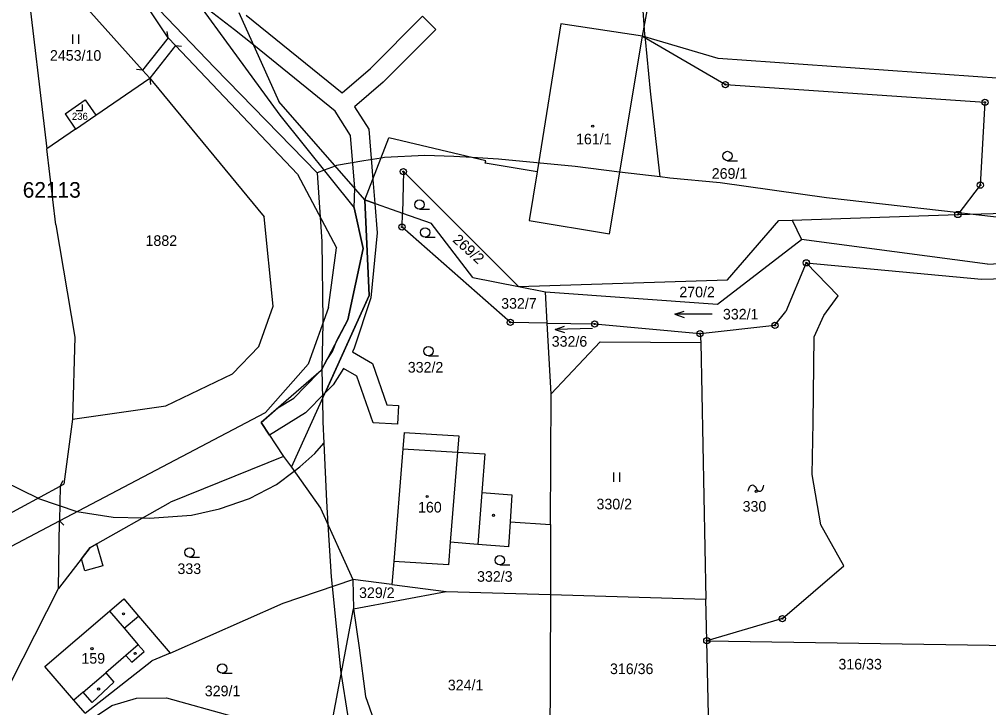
# Model space of a CAD drawing. Extents: x -546762 to -540209, y -1046851 to -1035694.
# Drawn here: x -542383.9 to -542228.7, y -1038905.5 to -1038795.4 of the extents above; entities that cross this region are included whole.
import ezdxf

# ---------------------------------------------------------------- set-up
doc = ezdxf.new("R2010")
doc.units = 0
for name, color, linetype in [('Vrstva 1', 7, 'Continuous'), ('Vrstva 18', 7, 'Continuous'), ('Vrstva 19', 7, 'Continuous'), ('Vrstva 24', 7, 'Continuous'), ('Vrstva 25', 7, 'Continuous'), ('Vrstva 26', 7, 'Continuous'), ('Vrstva 3', 7, 'Continuous'), ('Vrstva 30', 7, 'Continuous'), ('Vrstva 37', 7, 'Continuous'), ('Vrstva 4', 7, 'Continuous'), ('Vrstva 52', 7, 'Continuous'), ('Vrstva 53', 7, 'Continuous'), ('Vrstva 6', 7, 'Continuous')]:
    doc.layers.add(name, color=color, linetype=linetype)

msp = doc.modelspace()

# ---------------------------------------------------------------- linework, layer by layer
at = {"layer": 'Vrstva 1'}
for p, q in [((-542289.4, -1038829.68), (-542284.12, -1038798.06)), ((-542302.25, -1038827.55), (-542289.4, -1038829.68)), ((-542252.83, -1038839.61), (-542257.91, -1038834.34)), ((-542255.11, -1038842.75), (-542252.83, -1038839.61)), ((-542256.65, -1038846.21), (-542255.11, -1038842.75)), ((-542256.83, -1038859.88), (-542256.65, -1038846.21)), ((-542256.95, -1038868.24), (-542256.83, -1038859.88)), ((-542255.57, -1038876.26), (-542256.95, -1038868.24)), ((-542251.88, -1038882.83), (-542255.57, -1038876.26)), ((-542261.74, -1038891.29), (-542251.88, -1038882.83)), ((-542273.83, -1038894.83), (-542273.98, -1038888.19)), ((-542261.74, -1038891.29), (-542273.83, -1038894.83)), ((-542273.83, -1038894.83), (-542140.34, -1038896.94)), ((-542273.49, -1038910.46), (-542273.83, -1038894.83))]:
    msp.add_line(p, q, dxfattribs=at)
for points in [[(-542360.08, -1038798.3), (-542376.28, -1038773.87)], [(-542284.12, -1038798.06), (-542280.6, -1038779)], [(-542363.14, -1038781.96), (-542342.19, -1038810.68)], [(-542364.14, -1038803.52), (-542379.8, -1038785.97)], [(-542382.73, -1038788.59), (-542379.48, -1038816.1)], [(-542348.72, -1038794.24), (-542342.34, -1038808.53)], [(-542358.91, -1038799.54), (-542360.08, -1038798.3)], [(-542271.99, -1038801.64), (-542284.12, -1038798.06)], [(-542284.12, -1038798.06), (-542270.86, -1038805.8)], [(-542339.35, -1038820.17), (-542358.91, -1038799.54)], [(-542213.03, -1038805.77), (-542271.99, -1038801.64)], [(-542364.14, -1038803.52), (-542363, -1038804.8)], [(-542371.63, -1038810.72), (-542363, -1038804.8)], [(-542363, -1038804.8), (-542362.55, -1038805.31)], [(-542362.55, -1038805.31), (-542344.69, -1038826.96)], [(-542270.86, -1038805.8), (-542229.31, -1038808.64)], [(-542376.57, -1038810.49), (-542373.32, -1038808.26)], [(-542373.32, -1038808.26), (-542371.63, -1038810.72)], [(-542328.57, -1038824.27), (-542342.34, -1038808.53)], [(-542229.31, -1038808.64), (-542230.06, -1038821.9)], [(-542376.57, -1038810.49), (-542374.88, -1038812.95)], [(-542374.88, -1038812.95), (-542371.63, -1038810.72)], [(-542342.19, -1038810.68), (-542330.3, -1038825.51)], [(-542374.88, -1038812.95), (-542379.48, -1038816.1)], [(-542328.57, -1038824.27), (-542324.71, -1038814.32)], [(-542309.22, -1038818.02), (-542324.71, -1038814.32)], [(-542378.05, -1038828.27), (-542379.48, -1038816.1)], [(-542309.29, -1038818.41), (-542309.22, -1038818.02)], [(-542300.99, -1038819.75), (-542309.29, -1038818.41)], [(-542303.96, -1038838.14), (-542322.41, -1038819.74), (-542322.56, -1038826.38)], [(-542300.99, -1038819.75), (-542302.25, -1038827.55)], [(-542339.35, -1038820.17), (-542333.12, -1038831.96)], [(-542230.06, -1038821.9), (-542233.65, -1038826.6)], [(-542327.87, -1038839.58), (-542328.57, -1038824.27)], [(-542328.57, -1038824.27), (-542322.56, -1038826.38)], [(-542330.3, -1038825.51), (-542328.83, -1038832.04)], [(-542233.65, -1038826.6), (-542213.02, -1038826.03)], [(-542343.26, -1038841.29), (-542344.69, -1038826.96)], [(-542299.4, -1038843.98), (-542305.28, -1038843.87), (-542322.61, -1038828.61), (-542322.56, -1038826.38)], [(-542322.56, -1038826.38), (-542317.97, -1038828)], [(-542270.5, -1038837.04), (-542262.31, -1038827.56)], [(-542262.31, -1038827.56), (-542260.18, -1038827.49)], [(-542260.18, -1038827.49), (-542233.65, -1038826.6)], [(-542378.05, -1038828.27), (-542375, -1038846.26)], [(-542311.31, -1038836.7), (-542317.97, -1038828)], [(-542272.12, -1038840.96), (-542258.65, -1038830.6)], [(-542228.9, -1038834.54), (-542258.65, -1038830.6)], [(-542334.4, -1038841.47), (-542333.12, -1038831.96)], [(-542328.83, -1038832.04), (-542331.28, -1038843.49)], [(-542228.9, -1038834.54), (-542202.62, -1038833.12)], [(-542257.91, -1038834.34), (-542261.17, -1038842.12)], [(-542257.91, -1038834.34), (-542229.87, -1038836.96)], [(-542311.31, -1038836.7), (-542303.96, -1038838.14)], [(-542303.96, -1038838.14), (-542270.5, -1038837.04)], [(-542229.87, -1038836.96), (-542203.18, -1038836.22)], [(-542303.96, -1038838.14), (-542299.68, -1038838.97)], [(-542340.34, -1038867.07), (-542327.87, -1038839.58)], [(-542299.68, -1038838.97), (-542272.12, -1038840.96)], [(-542299.4, -1038843.98), (-542299.68, -1038838.97)], [(-542345.52, -1038847.76), (-542343.26, -1038841.29)], [(-542334.4, -1038841.47), (-542337.63, -1038850.58)], [(-542274.91, -1038845.68), (-542262.93, -1038844.34), (-542261.17, -1038842.12)], [(-542331.28, -1038843.49), (-542335.59, -1038851.6)], [(-542299.4, -1038843.98), (-542291.8, -1038844.13), (-542274.91, -1038845.68)], [(-542298.77, -1038855.33), (-542299.4, -1038843.98)], [(-542375, -1038846.26), (-542375.37, -1038859.39)], [(-542274.91, -1038845.68), (-542274.78, -1038847.1)], [(-542349.77, -1038852.1), (-542345.52, -1038847.76)], [(-542290.89, -1038847.01), (-542298.77, -1038855.33)], [(-542290.89, -1038847.01), (-542274.78, -1038847.1)], [(-542274.78, -1038847.1), (-542273.98, -1038888.19)], [(-542344.49, -1038858.28), (-542337.63, -1038850.58)], [(-542360.42, -1038857.25), (-542349.77, -1038852.1)], [(-542335.59, -1038851.6), (-542345.17, -1038859.89)], [(-542298.84, -1038876.22), (-542298.77, -1038855.33)], [(-542375.37, -1038859.39), (-542360.42, -1038857.25)], [(-542377.43, -1038875.62), (-542344.49, -1038858.28)], [(-542375.37, -1038859.39), (-542376.75, -1038869.78)], [(-542345.17, -1038859.89), (-542341.59, -1038865.32)], [(-542322.28, -1038861.48), (-542322.49, -1038864.12)], [(-542322.28, -1038861.48), (-542313.52, -1038862.02)], [(-542313.52, -1038862.02), (-542313.73, -1038864.66)], [(-542322.49, -1038864.12), (-542323.94, -1038882.13)], [(-542313.73, -1038864.66), (-542309.34, -1038864.93)], [(-542309.34, -1038864.93), (-542309.84, -1038871.11)], [(-542341.59, -1038865.32), (-542359.68, -1038872.68)], [(-542341.59, -1038865.32), (-542340.34, -1038867.07)], [(-542340.34, -1038867.07), (-542335.69, -1038873.59)], [(-542377.33, -1038870.1), (-542376.75, -1038869.78)], [(-542386.79, -1038875.23), (-542377.33, -1038870.1)], [(-542309.84, -1038871.11), (-542305.07, -1038871.49)], [(-542372.52, -1038879.89), (-542359.68, -1038872.68)], [(-542305.07, -1038871.49), (-542305.33, -1038875.82)], [(-542335.69, -1038873.59), (-542330.5, -1038885.02)], [(-542387.12, -1038880.72), (-542377.43, -1038875.62)], [(-542377.61, -1038886.5), (-542377.43, -1038875.62)], [(-542305.33, -1038875.82), (-542305.58, -1038879.81)], [(-542305.33, -1038875.82), (-542298.84, -1038876.22)], [(-542298.84, -1038876.22), (-542298.87, -1038887.45)], [(-542314.89, -1038879.06), (-542315.18, -1038882.67)], [(-542310.5, -1038879.41), (-542314.89, -1038879.06)], [(-542372.52, -1038879.89), (-542377.61, -1038886.5)], [(-542305.58, -1038879.81), (-542310.5, -1038879.41)], [(-542323.94, -1038882.13), (-542324.24, -1038885.83)], [(-542315.18, -1038882.67), (-542323.94, -1038882.13)], [(-542341.67, -1038888.8), (-542330.5, -1038885.02)], [(-542330.5, -1038885.02), (-542330.4, -1038889.72)], [(-542324.24, -1038885.83), (-542330.5, -1038885.02)], [(-542388.99, -1038908.78), (-542377.61, -1038886.5)], [(-542324.24, -1038885.83), (-542315.53, -1038886.96)], [(-542369.46, -1038890.1), (-542367.18, -1038888.15)], [(-542367.18, -1038888.15), (-542364.83, -1038890.88)], [(-542330.4, -1038889.72), (-542315.53, -1038886.96)], [(-542315.53, -1038886.96), (-542298.87, -1038887.45)], [(-542298.87, -1038887.45), (-542298.95, -1038911.66)], [(-542298.87, -1038887.45), (-542273.98, -1038888.19)], [(-542359.74, -1038896.82), (-542341.67, -1038888.8)], [(-542334.18, -1038909.82), (-542330.4, -1038889.72)], [(-542330.4, -1038889.72), (-542329.46, -1038896), (-542328.49, -1038903.78), (-542324.44, -1038915.15)], [(-542379.78, -1038898.95), (-542369.46, -1038890.1)], [(-542364.83, -1038890.88), (-542359.74, -1038896.82)], [(-542359.74, -1038896.82), (-542362.65, -1038898.03)], [(-542375.16, -1038904.34), (-542379.78, -1038898.95)], [(-542373.37, -1038906.43), (-542362.65, -1038898.03)], [(-542373.37, -1038906.43), (-542375.16, -1038904.34)]]:
    msp.add_lwpolyline(points, dxfattribs=at)
at = {"layer": 'Vrstva 24'}
for centre, radius in [((-542270.86, -1038805.8), 0.5), ((-542270.86, -1038805.8), 0.1), ((-542229.31, -1038808.64), 0.5), ((-542229.31, -1038808.64), 0.1), ((-542322.41, -1038819.74), 0.5), ((-542322.41, -1038819.74), 0.1), ((-542230.06, -1038821.9), 0.5), ((-542230.06, -1038821.9), 0.1), ((-542233.65, -1038826.6), 0.5), ((-542233.65, -1038826.6), 0.1), ((-542322.61, -1038828.61), 0.5), ((-542322.61, -1038828.61), 0.1), ((-542257.91, -1038834.34), 0.5), ((-542257.91, -1038834.34), 0.1), ((-542305.28, -1038843.87), 0.5), ((-542305.28, -1038843.87), 0.1), ((-542291.8, -1038844.13), 0.5), ((-542291.8, -1038844.13), 0.1), ((-542262.93, -1038844.34), 0.5), ((-542262.93, -1038844.34), 0.1), ((-542274.91, -1038845.68), 0.5), ((-542274.91, -1038845.68), 0.1), ((-542261.74, -1038891.29), 0.5), ((-542261.74, -1038891.29), 0.1), ((-542273.83, -1038894.83), 0.5), ((-542273.83, -1038894.83), 0.1)]:
    msp.add_circle(centre, radius, dxfattribs=at)
at = {"layer": 'Vrstva 25'}
for p, q in [((-542375.34, -1038799.29), (-542375.34, -1038797.79)), ((-542374.34, -1038799.29), (-542374.34, -1038797.79)), ((-542270.53, -1038817.99), (-542268.93, -1038817.99)), ((-542319.84, -1038825.76), (-542318.24, -1038825.76)), ((-542318.93, -1038830.23), (-542317.33, -1038830.23)), ((-542318.39, -1038849.21), (-542316.79, -1038849.21)), ((-542288.74, -1038869.42), (-542288.74, -1038867.92)), ((-542287.74, -1038869.42), (-542287.74, -1038867.92)), ((-542356.62, -1038881.46), (-542355.02, -1038881.46)), ((-542306.98, -1038882.7), (-542305.38, -1038882.7)), ((-542351.41, -1038900.04), (-542349.81, -1038900.04))]:
    msp.add_line(p, q, dxfattribs=at)
for points in [[(-542374.78, -1038809.98), (-542373.78, -1038809.98), (-542373.78, -1038808.98)], [(-542278.95, -1038842.58), (-542277.45, -1038842.07)], [(-542272.95, -1038842.54), (-542278.95, -1038842.58), (-542277.45, -1038843.07)], [(-542298.11, -1038845.03), (-542296.62, -1038844.49)], [(-542292.11, -1038844.85), (-542298.11, -1038845.03), (-542296.59, -1038845.49)]]:
    msp.add_lwpolyline(points, dxfattribs=at)
for centre, radius in [((-542292.1, -1038812.46), 0.175), ((-542270.53, -1038817.24), 0.75), ((-542319.84, -1038825.01), 0.75), ((-542318.93, -1038829.48), 0.75), ((-542318.39, -1038848.46), 0.75), ((-542318.59, -1038871.74), 0.175), ((-542307.97, -1038874.76), 0.175), ((-542356.62, -1038880.71), 0.75), ((-542306.98, -1038881.95), 0.75), ((-542367.21, -1038890.53), 0.175), ((-542372.26, -1038896.1), 0.175), ((-542365.35, -1038896.87), 0.175), ((-542351.41, -1038899.29), 0.75), ((-542371.2, -1038902.57), 0.175)]:
    msp.add_circle(centre, radius, dxfattribs=at)
msp.add_open_spline([(-542267.19, -1038870.91), (-542267.16, -1038870.74), (-542267.1, -1038870.48), (-542266.97, -1038870.18), (-542266.78, -1038869.99), (-542266.5, -1038869.86), (-542266.22, -1038870), (-542265.97, -1038870.24), (-542265.91, -1038870.58), (-542265.66, -1038870.82), (-542265.38, -1038870.96), (-542265.1, -1038870.83), (-542264.91, -1038870.64), (-542264.78, -1038870.34), (-542264.72, -1038870.08), (-542264.69, -1038869.91)], degree=3, dxfattribs=at)
at = {"layer": 'Vrstva 26'}
for p, q in [((-542360.08, -1038798.3), (-542360.2, -1038797.31)), ((-542358.91, -1038799.54), (-542357.92, -1038799.66)), ((-542364.14, -1038803.52), (-542365.13, -1038803.4)), ((-542363, -1038804.8), (-542362.88, -1038805.79)), ((-542377.33, -1038870.1), (-542376.89, -1038869.2)), ((-542377.43, -1038875.62), (-542376.74, -1038876.34))]:
    msp.add_line(p, q, dxfattribs=at)
at = {"layer": 'Vrstva 3'}
for points in [[(-542297.18, -1038796.09), (-542300.99, -1038819.75)], [(-542284.12, -1038798.06), (-542297.18, -1038796.09)], [(-542289.4, -1038829.68), (-542284.12, -1038798.06)], [(-542300.99, -1038819.75), (-542302.25, -1038827.55)], [(-542302.25, -1038827.55), (-542289.4, -1038829.68)], [(-542257.91, -1038834.34), (-542261.17, -1038842.12)], [(-542252.83, -1038839.61), (-542257.91, -1038834.34)], [(-542255.11, -1038842.75), (-542252.83, -1038839.61)], [(-542274.91, -1038845.68), (-542262.93, -1038844.34), (-542261.17, -1038842.12)], [(-542256.65, -1038846.21), (-542255.11, -1038842.75)], [(-542274.91, -1038845.68), (-542274.78, -1038847.1)], [(-542256.83, -1038859.88), (-542256.65, -1038846.21)], [(-542274.78, -1038847.1), (-542273.98, -1038888.19)], [(-542256.95, -1038868.24), (-542256.83, -1038859.88)], [(-542322.49, -1038864.12), (-542323.94, -1038882.13)], [(-542322.49, -1038864.12), (-542313.73, -1038864.66)], [(-542313.73, -1038864.66), (-542314.89, -1038879.06)], [(-542255.57, -1038876.26), (-542256.95, -1038868.24)], [(-542251.88, -1038882.83), (-542255.57, -1038876.26)], [(-542314.89, -1038879.06), (-542315.18, -1038882.67)], [(-542315.18, -1038882.67), (-542323.94, -1038882.13)], [(-542261.74, -1038891.29), (-542251.88, -1038882.83)], [(-542273.83, -1038894.83), (-542273.98, -1038888.19)], [(-542379.78, -1038898.95), (-542369.46, -1038890.1)], [(-542369.46, -1038890.1), (-542367.11, -1038892.83)], [(-542261.74, -1038891.29), (-542273.83, -1038894.83)], [(-542367.11, -1038892.83), (-542364.84, -1038895.49)], [(-542364.84, -1038895.49), (-542366.81, -1038897.18)], [(-542366.81, -1038897.18), (-542370.04, -1038899.95)], [(-542375.16, -1038904.34), (-542379.78, -1038898.95)], [(-542373.68, -1038903.07), (-542370.04, -1038899.95)], [(-542373.68, -1038903.07), (-542375.16, -1038904.34)]]:
    msp.add_lwpolyline(points, dxfattribs=at)
at = {"layer": 'Vrstva 30'}
for p, q in [((-542349.42, -1038797.05), (-542355.67, -1038792.2)), ((-542346.36, -1038799.52), (-542349.42, -1038797.05)), ((-542333.31, -1038810.07), (-542346.36, -1038799.52)), ((-542330.89, -1038813.93), (-542333.31, -1038810.07)), ((-542330.19, -1038822.41), (-542330.89, -1038813.93)), ((-542330.3, -1038825.51), (-542330.19, -1038822.41))]:
    msp.add_line(p, q, dxfattribs=at)
for points in [[(-542347.56, -1038794.69), (-542332.2, -1038807.11), (-542327.67, -1038803.24), (-542319.32, -1038794.87), (-542317.2, -1038796.99), (-542325.63, -1038805.44), (-542330.21, -1038809.36), (-542327.95, -1038812.95), (-542327.3, -1038821), (-542326.99, -1038824.83), (-542328.57, -1038824.27), (-542327.87, -1038839.58), (-542334.93, -1038855.15), (-542338.06, -1038858.35), (-542343.82, -1038861.94), (-542345.17, -1038859.89), (-542342.49, -1038857.57), (-542339.96, -1038855.99), (-542336.03, -1038851.98), (-542335.59, -1038851.6), (-542334.72, -1038849.96), (-542333.77, -1038848.51), (-542333.04, -1038846.8), (-542331.28, -1038843.49), (-542328.83, -1038832.04), (-542330.3, -1038825.51)], [(-542327.37, -1038850.43), (-542325.05, -1038857.08), (-542323.18, -1038857.18), (-542323.33, -1038860.17), (-542327.23, -1038859.98), (-542329.83, -1038852.47), (-542331.97, -1038851.23), (-542333.67, -1038853.86), (-542334.93, -1038855.15), (-542327.87, -1038839.58), (-542328.57, -1038824.27), (-542326.99, -1038824.83), (-542326.6, -1038829.53), (-542327.62, -1038839.94), (-542330.28, -1038848.01), (-542330.54, -1038848.6), (-542327.37, -1038850.43)], [(-542370.5, -1038882.86), (-542373.39, -1038883.67), (-542373.93, -1038881.73), (-542372.52, -1038879.89), (-542371.53, -1038879.33), (-542370.5, -1038882.86)], [(-542365.15, -1038904.02), (-542360.32, -1038904), (-542349.58, -1038906.96), (-542350.37, -1038909.85), (-542360.72, -1038907), (-542362.49, -1038907.01), (-542364.71, -1038907.02), (-542365.07, -1038907.13), (-542367.77, -1038907.94), (-542375.03, -1038912.82), (-542376.24, -1038913.45), (-542377.96, -1038912.97), (-542379.08, -1038916.97), (-542390.18, -1038910.54), (-542388.99, -1038908.78), (-542382.33, -1038911.62), (-542379.91, -1038913.02), (-542379.76, -1038912.72), (-542378.96, -1038913.06), (-542376.59, -1038910.25), (-542369.07, -1038905.2), (-542365.15, -1038904.02)]]:
    msp.add_lwpolyline(points, dxfattribs=at)
at = {"layer": 'Vrstva 37'}
for centre in [(-542292.1, -1038812.46), (-542265.94, -1038870.91), (-542318.59, -1038871.74), (-542372.26, -1038896.1)]:
    msp.add_circle(centre, 0.175, dxfattribs=at)
at = {"layer": 'Vrstva 4'}
msp.add_line((-542284.12, -1038798.06), (-542297.18, -1038796.09), dxfattribs=at)
for points in [[(-542297.18, -1038796.09), (-542300.99, -1038819.75)], [(-542360.08, -1038798.3), (-542364.14, -1038803.52)], [(-542358.91, -1038799.54), (-542363, -1038804.8)], [(-542322.49, -1038864.12), (-542313.73, -1038864.66)], [(-542313.73, -1038864.66), (-542314.89, -1038879.06)], [(-542377.33, -1038870.1), (-542377.43, -1038875.62)], [(-542309.84, -1038871.11), (-542310.5, -1038879.41)], [(-542369.46, -1038890.1), (-542367.11, -1038892.83)], [(-542367.11, -1038892.83), (-542364.83, -1038890.88)], [(-542367.11, -1038892.83), (-542364.84, -1038895.49)], [(-542364.84, -1038895.49), (-542366.81, -1038897.18)], [(-542363.92, -1038896.55), (-542364.84, -1038895.49)], [(-542366.81, -1038897.18), (-542370.04, -1038899.95)], [(-542366.81, -1038897.18), (-542365.9, -1038898.25)], [(-542365.9, -1038898.25), (-542363.92, -1038896.55)], [(-542373.68, -1038903.07), (-542370.04, -1038899.95)], [(-542370.04, -1038899.95), (-542368.73, -1038901.47)], [(-542368.73, -1038901.47), (-542372.25, -1038904.74)], [(-542373.68, -1038903.07), (-542375.16, -1038904.34)], [(-542372.25, -1038904.74), (-542373.68, -1038903.07)]]:
    msp.add_lwpolyline(points, dxfattribs=at)
at = {"layer": 'Vrstva 52'}
for points in [[(-542387.78, -1038701.12), (-542389.12, -1038709.64), (-542389.57, -1038717.41), (-542389.87, -1038726.22), (-542389.5, -1038735.48), (-542388.61, -1038743.85), (-542387.96, -1038748.24), (-542387.71, -1038749.98), (-542386.22, -1038755.81), (-542383.68, -1038763.28), (-542380.69, -1038770), (-542376.36, -1038776.73), (-542367.4, -1038787.64), (-542366.59, -1038788.49), (-542352.57, -1038803.11), (-542336.21, -1038819.92)], [(-542282.83, -1038806.87), (-542283.65, -1038798.54), (-542283.73, -1038797.75), (-542283.89, -1038795.51), (-542284.33, -1038789.38), (-542284.43, -1038778.99), (-542284.48, -1038773.69), (-542284.48, -1038773.63), (-542284.83, -1038753.92)], [(-542281.32, -1038820.59), (-542282.83, -1038806.87)], [(-542281.32, -1038820.59), (-542287.81, -1038819.8), (-542294.93, -1038818.94), (-542307.17, -1038817.75), (-542311.42, -1038817.5), (-542314.34, -1038817.32), (-542318.95, -1038817.15), (-542325.43, -1038817.49), (-542325.97, -1038817.57), (-542328.76, -1038818.01), (-542333.12, -1038818.77), (-542333.32, -1038818.84), (-542335.11, -1038819.51), (-542336.21, -1038819.92)], [(-542336.21, -1038819.92), (-542335.73, -1038827.03), (-542335.46, -1038830.94), (-542335.31, -1038843.65), (-542335.32, -1038844.06), (-542335.46, -1038851.27), (-542335.46, -1038851.35), (-542335.37, -1038856.12), (-542335.31, -1038859.79), (-542335.15, -1038863.19)], [(-542104.97, -1038858.58), (-542116.73, -1038853.61), (-542120.13, -1038852.16), (-542121.34, -1038851.64), (-542130.98, -1038847.53), (-542132.67, -1038846.81), (-542146.79, -1038841.32), (-542159.34, -1038837.66), (-542164.18, -1038836.45), (-542177.11, -1038833.21), (-542179.63, -1038832.84), (-542195.15, -1038830.6), (-542214.49, -1038828.51), (-542231.66, -1038826.54), (-542233.45, -1038826.34), (-542254.68, -1038823.91), (-542271.67, -1038821.56), (-542279.77, -1038820.78), (-542281.32, -1038820.59)], [(-542402.72, -1038851.35), (-542402.63, -1038851.48), (-542402.15, -1038852.18), (-542397.79, -1038858.52), (-542393.01, -1038864.2), (-542392.94, -1038864.25), (-542386.74, -1038869.13), (-542386.43, -1038869.28), (-542380.87, -1038872.02), (-542380.79, -1038872.06), (-542374.67, -1038874.16), (-542368.84, -1038875.05), (-542364.12, -1038875.17)], [(-542356.3, -1038874.75), (-542351.82, -1038873.71), (-542347.04, -1038872.06), (-542342.7, -1038869.82), (-542339.9, -1038867.69), (-542338.97, -1038866.98), (-542336.58, -1038864.89), (-542335.15, -1038863.19)], [(-542335.15, -1038863.19), (-542334.72, -1038872.49), (-542334.49, -1038876.24), (-542333.97, -1038884.6), (-542333.81, -1038886.14), (-542332.42, -1038899.98), (-542332.38, -1038900.24), (-542330.33, -1038913.06)], [(-542364.12, -1038875.17), (-542363.02, -1038875.2), (-542356.3, -1038874.75)]]:
    msp.add_lwpolyline(points, dxfattribs=at)
at = {"layer": 'Vrstva 6'}
msp.add_lwpolyline([(-542260.18, -1038827.49), (-542258.65, -1038830.6)], dxfattribs=at)

# ---------------------------------------------------------------- texts
at = {"layer": 'Vrstva 18'}
for s, p in [('2453/10', (-542378.98, -1038801.99)), ('269/1', (-542273.04, -1038820.89)), ('1882', (-542363.68, -1038831.63)), ('270/2', (-542278.23, -1038839.86)), ('332/7', (-542306.75, -1038841.69)), ('332/1', (-542271.25, -1038843.41)), ('332/6', (-542298.66, -1038847.77)), ('332/2', (-542321.7, -1038851.91)), ('330/2', (-542291.49, -1038873.81)), ('333', (-542358.57, -1038884.16)), ('332/3', (-542310.61, -1038885.4)), ('329/2', (-542329.5, -1038888)), ('316/33', (-542252.76, -1038899.44)), ('316/36', (-542289.33, -1038900.18)), ('329/1', (-542354.19, -1038903.72)), ('324/1', (-542315.29, -1038902.78))]:
    msp.add_text(s, height=1.7, dxfattribs=at).set_placement(p)
msp.add_text('269/2', height=1.7, rotation=317.9244, dxfattribs=at).set_placement((-542314.64, -1038830.84))
at = {"layer": 'Vrstva 19'}
for s, height, p in [('236', 1.14, (-542375.46, -1038811.46)), ('161/1', 1.7, (-542294.77, -1038815.37)), ('160', 1.7, (-542320.06, -1038874.31)), ('330', 1.7, (-542268.1, -1038874.18)), ('159', 1.7, (-542373.95, -1038898.51))]:
    msp.add_text(s, height=height, dxfattribs=at).set_placement(p)
at = {"layer": 'Vrstva 53'}
msp.add_text('62113', height=2.5, dxfattribs=at).set_placement((-542383.34, -1038823.91))

doc.saveas('drawing.dxf')
